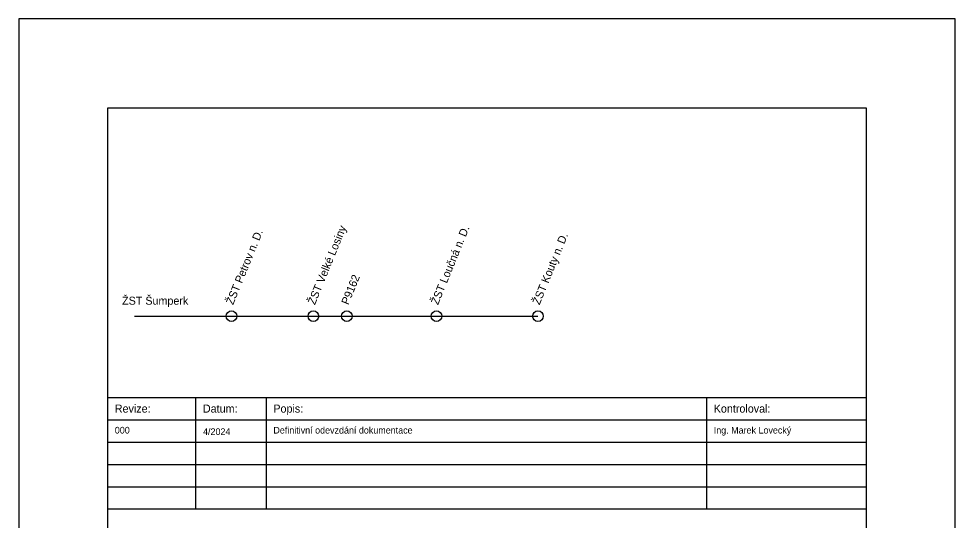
# Model space of a CAD drawing. Extents: x 1391 to 5528, y -6194 to 565.
# Drawn here: x 3925.6 to 4135.6, y -3614 to -3501.5 of the extents above; entities that cross this region are included whole.
import ezdxf

# ---------------------------------------------------------------- set-up
doc = ezdxf.new("R2010")
doc.units = 0
for name, color, linetype in [('Default', 7, 'Continuous'), ('Vrstva 1', 7, 'Continuous'), ('Vrstva 11', 7, 'Continuous'), ('Vrstva 4', 7, 'Continuous'), ('Vrstva 7', 7, 'Continuous')]:
    doc.layers.add(name, color=color, linetype=linetype)

msp = doc.modelspace()

# ---------------------------------------------------------------- linework, layer by layer
at = {"layer": 'Default'}
msp.add_lwpolyline([(3925.56, -3798.54), (4135.56, -3798.54), (4135.56, -3501.54), (3925.56, -3501.54)], close=True, dxfattribs=at)
at = {"layer": 'Vrstva 1'}
msp.add_lwpolyline([(3945.56, -3521.54), (4115.56, -3521.54), (4115.56, -3781.54), (3945.56, -3781.54)], close=True, dxfattribs=at)
at = {"layer": 'Vrstva 11'}
msp.add_lwpolyline([(3951.49, -3568.25), (4041.99, -3568.25)], dxfattribs=at)
for centre in [(3973.28, -3568.25), (3991.63, -3568.25), (3991.63, -3568.25), (3999.14, -3568.25), (4019.24, -3568.25), (4019.24, -3568.25), (4041.99, -3568.25), (4041.99, -3568.25)]:
    msp.add_circle(centre, 1.2, dxfattribs=at)
at = {"layer": 'Vrstva 4'}
for p, q in [((3965.31, -3611.54), (3965.31, -3586.54)), ((3981.11, -3611.54), (3981.11, -3586.54)), ((4079.86, -3611.54), (4079.86, -3586.54)), ((3945.56, -3591.54), (4115.56, -3591.54)), ((3945.56, -3596.54), (4115.56, -3596.54)), ((3945.56, -3601.54), (4115.56, -3601.54)), ((3945.56, -3606.54), (4115.56, -3606.54))]:
    msp.add_line(p, q, dxfattribs=at)
msp.add_lwpolyline([(3945.56, -3586.54), (4115.56, -3586.54), (4115.56, -3611.54), (3945.56, -3611.54)], close=True, dxfattribs=at)

# ---------------------------------------------------------------- texts
for s, height, p in [('Revize:', 1.8, (3947.11, -3589.89)), ('Datum:', 1.8, (3966.86, -3589.89)), ('Popis:', 1.8, (3982.66, -3589.89)), ('Kontroloval:', 1.8, (4081.41, -3589.89)), ('000', 1.5, (3947.11, -3594.59)), ('Definitivní odevzdání dokumentace', 1.5, (3982.66, -3594.59)), ('Ing. Marek Lovecký', 1.5, (4081.41, -3594.59)), ('4/2024', 1.5, (3966.89, -3594.91))]:
    msp.add_text(s, height=height, dxfattribs=at).set_placement(p)
at = {"layer": 'Vrstva 7'}
for s, p in [('ŽST Velké Losiny', (3991.97, -3565.85)), ('ŽST Loučná n. D.', (4019.58, -3565.85)), ('ŽST Petrov n. D.', (3973.63, -3565.85)), ('ŽST Kouty n. D.', (4042.34, -3565.85)), ('P9162', (3999.48, -3565.85))]:
    msp.add_text(s, height=1.8, rotation=67.8731, dxfattribs=at).set_placement(p)
msp.add_text('ŽST Šumperk', height=1.8, dxfattribs=at).set_placement((3948.74, -3565.69))

doc.saveas('drawing.dxf')
